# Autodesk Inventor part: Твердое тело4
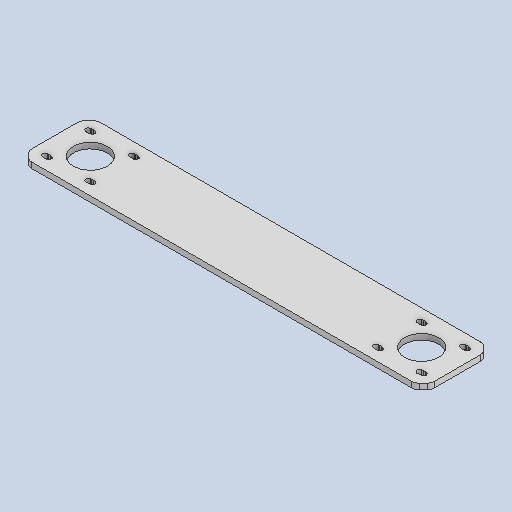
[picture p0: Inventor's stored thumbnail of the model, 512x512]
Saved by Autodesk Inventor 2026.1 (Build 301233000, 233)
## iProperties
Created: 2026-01
Part Number: Твердое тело4
Material: Типовые
Document SubType Name: Modeling
Designer: Yury Melnikov
Density: 1 g/cm^3
Appearance: По умолчанию
Author: Yury Melnikov
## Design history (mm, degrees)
derived "Nema17H44.ipt"
feature "Твердое тело4::Nema17H44.ipt" dims "d0" = 10
tag "Элемент создания тегов1"
node "Твердое тело4"
